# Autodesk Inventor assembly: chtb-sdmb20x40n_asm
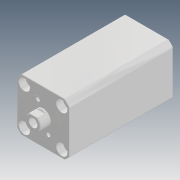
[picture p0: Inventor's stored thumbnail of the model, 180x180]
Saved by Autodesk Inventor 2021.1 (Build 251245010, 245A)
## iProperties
Company: Microsoft
Created: 2018-05
Part Number: chtb-sdmb20x40n_asm
Description: STEP AP214
Document SubType Name: Assembly
Designer: user
Title: chtb-sdmb20x40n_asm.STEP
Author: Windows
Revision Number: ÈÎºÎ
Sending System: SolidWorks 2015
Preprocessor: SwSTEP 2.0
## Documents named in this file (4)
- D:\Vault_2016\Projekty\Clamptek\Hydraulic\CHTB\CHTB-20\Inventor\CHTB-SDMB20x40N\chtb-sdmb20x40n_asm.iam
- D:\Vault_2016\Projekty\Clamptek\Hydraulic\CHTB\CHTB-20\Inventor\CHTB-SDMB20x40N\CHTB-SDMB20X40NBT.ipt
- D:\Vault_2016\Projekty\Clamptek\Hydraulic\CHTB\CHTB-20\Inventor\CHTB-SDMB20x40N\CHTB-SDMB20X40NHSG.ipt
- D:\Vault_2016\Projekty\Clamptek\Hydraulic\CHTB\CHTB-20\Inventor\CHTB-SDMB20x40N\QG_3.ipt
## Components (3 placed, 3 different names)
1. CHTB-SDMB20X40NBT_1
2. CHTB-SDMB20X40NHSG_2
3. QG_3_3
